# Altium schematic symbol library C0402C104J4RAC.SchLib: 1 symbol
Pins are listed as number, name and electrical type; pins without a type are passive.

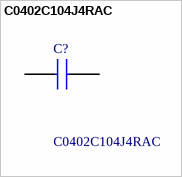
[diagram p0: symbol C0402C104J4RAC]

## C0402C104J4RAC
designator C?
Multilayer Ceramic Capacitors MLCC - SMD/SMT 16volts 0.1uF 5% X7R; Manufacturer_Name: Yageo Group; Geometry.Height: 0.55mm
footprint C0402C104J4RACTU
pins: 1, 2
